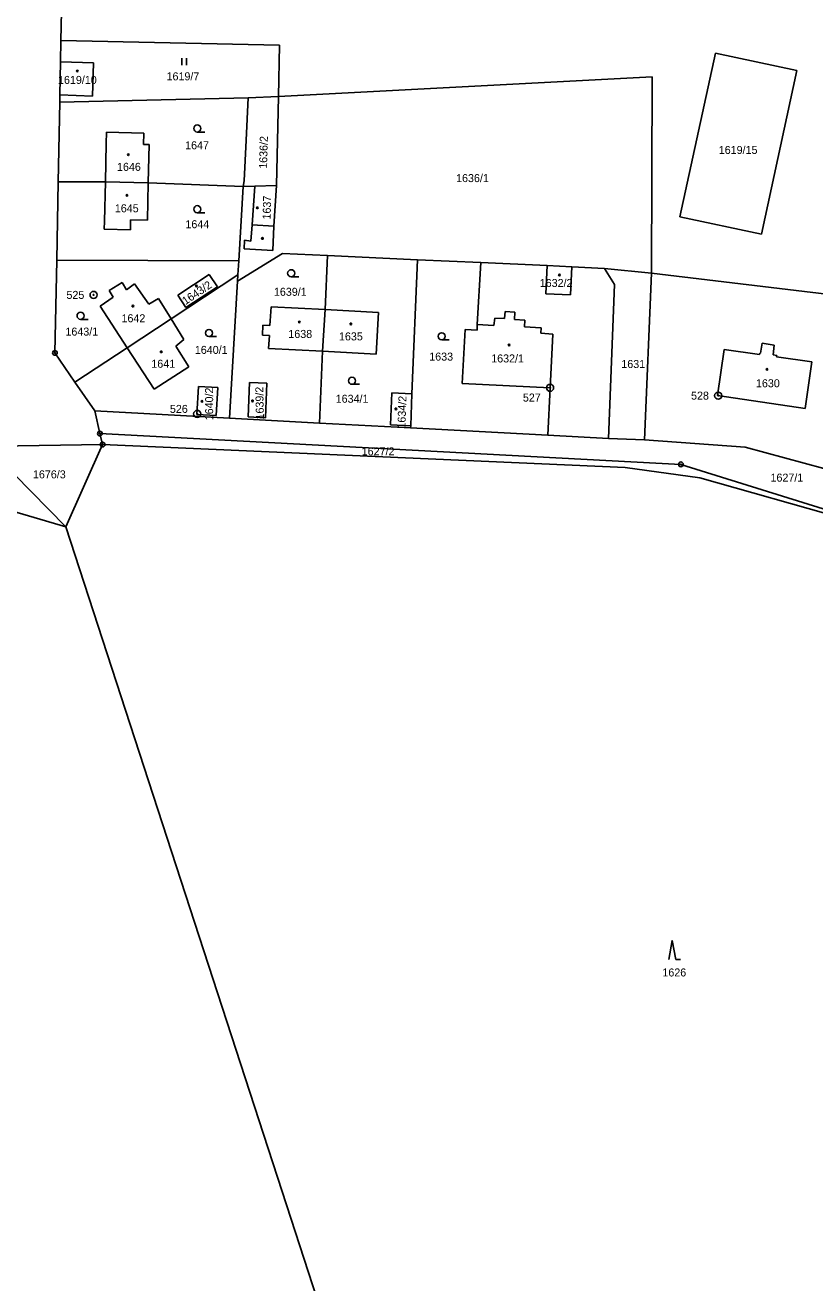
# Model space of a CAD drawing. Extents: x -763296 to -761805, y -1153670 to -1152034.
# Drawn here: x -762755.5 to -762587.9, y -1153075 to -1152808 of the extents above; entities that cross this region are included whole.
import ezdxf

# ---------------------------------------------------------------- set-up
doc = ezdxf.new("R2010")
doc.units = 0
for name, color, linetype in [('Vrstva 1', 7, 'Continuous'), ('Vrstva 13', 7, 'Continuous'), ('Vrstva 17', 7, 'Continuous'), ('Vrstva 18', 7, 'Continuous'), ('Vrstva 19', 7, 'Continuous'), ('Vrstva 24', 7, 'Continuous'), ('Vrstva 25', 7, 'Continuous'), ('Vrstva 4', 7, 'Continuous'), ('Vrstva 6', 7, 'Continuous')]:
    doc.layers.add(name, color=color, linetype=linetype)

msp = doc.modelspace()

# ---------------------------------------------------------------- linework, layer by layer
at = {"layer": 'Vrstva 1'}
for p, q in [((-762747.54, -1152790.8), (-762747.92, -1152811.23)), ((-762747.92, -1152811.23), (-762748.01, -1152815.75)), ((-762747.92, -1152811.23), (-762701.5, -1152812.19)), ((-762701.5, -1152812.19), (-762701.74, -1152823.08)), ((-762748.01, -1152815.75), (-762748.15, -1152822.79)), ((-762748.01, -1152815.75), (-762740.96, -1152815.98)), ((-762740.96, -1152815.98), (-762741.2, -1152823.03)), ((-762616.54, -1152848.68), (-762609.02, -1152813.88)), ((-762609.02, -1152813.88), (-762591.74, -1152817.6)), ((-762591.74, -1152817.6), (-762599.19, -1152852.35)), ((-762701.74, -1152823.08), (-762622.4, -1152818.96)), ((-762622.4, -1152818.96), (-762622.59, -1152860.62)), ((-762748.15, -1152822.79), (-762748.17, -1152824.33)), ((-762748.17, -1152824.33), (-762708.14, -1152823.41)), ((-762741.2, -1152823.03), (-762748.15, -1152822.79)), ((-762708.14, -1152823.41), (-762708.57, -1152832.36)), ((-762708.14, -1152823.41), (-762701.74, -1152823.08)), ((-762701.74, -1152823.08), (-762702.15, -1152842.02)), ((-762748.17, -1152824.33), (-762748.49, -1152841.23)), ((-762738.28, -1152833.12), (-762738.22, -1152830.72)), ((-762730.34, -1152830.91), (-762738.22, -1152830.72)), ((-762730.34, -1152830.91), (-762730.4, -1152833.31)), ((-762738.47, -1152841.24), (-762738.28, -1152833.12)), ((-762730.4, -1152833.31), (-762729.18, -1152833.33)), ((-762729.18, -1152833.33), (-762729.37, -1152841.45)), ((-762708.57, -1152832.36), (-762709.01, -1152840.99)), ((-762748.49, -1152841.23), (-762748.8, -1152857.83)), ((-762748.49, -1152841.23), (-762738.47, -1152841.24)), ((-762738.66, -1152849.55), (-762738.47, -1152841.24)), ((-762729.37, -1152841.45), (-762738.47, -1152841.24)), ((-762729.37, -1152841.45), (-762729.52, -1152849.37)), ((-762709.23, -1152842.19), (-762729.37, -1152841.45)), ((-762709.23, -1152842.19), (-762710.15, -1152858.02)), ((-762709.01, -1152840.99), (-762709.23, -1152842.19)), ((-762706.73, -1152842.13), (-762709.23, -1152842.19)), ((-762706.73, -1152842.13), (-762707.33, -1152850.33)), ((-762702.15, -1152842.02), (-762706.73, -1152842.13)), ((-762702.69, -1152850.62), (-762702.15, -1152842.02)), ((-762738.71, -1152851.29), (-762738.66, -1152849.55)), ((-762733.11, -1152849.28), (-762733.16, -1152851.42)), ((-762729.52, -1152849.37), (-762733.11, -1152849.28)), ((-762707.33, -1152850.33), (-762707.57, -1152853.84)), ((-762702.94, -1152855.84), (-762702.69, -1152850.62)), ((-762599.19, -1152852.35), (-762616.54, -1152848.68)), ((-762733.16, -1152851.42), (-762738.71, -1152851.29)), ((-762708.95, -1152853.61), (-762709.03, -1152855.49)), ((-762709.03, -1152855.49), (-762702.94, -1152855.84)), ((-762707.57, -1152853.84), (-762708.95, -1152853.61)), ((-762748.8, -1152857.83), (-762749.17, -1152877.56)), ((-762710.15, -1152858.02), (-762748.8, -1152857.83)), ((-762710.4, -1152862.29), (-762700.85, -1152856.46)), ((-762710.15, -1152858.02), (-762710.33, -1152860.99)), ((-762700.85, -1152856.46), (-762691.31, -1152856.9)), ((-762691.31, -1152856.9), (-762691.85, -1152868.36)), ((-762691.31, -1152856.9), (-762672.23, -1152857.78)), ((-762672.23, -1152857.78), (-762673.46, -1152886.23)), ((-762672.23, -1152857.78), (-762658.76, -1152858.39)), ((-762658.76, -1152858.39), (-762659.55, -1152871.55)), ((-762658.76, -1152858.39), (-762644.69, -1152858.99)), ((-762724.53, -1152870.33), (-762710.33, -1152860.99)), ((-762723.08, -1152865.32), (-762716.43, -1152860.9)), ((-762716.43, -1152860.9), (-762714.71, -1152863.51)), ((-762710.33, -1152860.99), (-762710.4, -1152862.29)), ((-762644.69, -1152858.99), (-762645.02, -1152865)), ((-762639.49, -1152859.25), (-762644.69, -1152858.99)), ((-762639.78, -1152865.25), (-762639.49, -1152859.25)), ((-762632.51, -1152859.6), (-762639.49, -1152859.25)), ((-762630.43, -1152863.01), (-762632.51, -1152859.6)), ((-762622.59, -1152860.62), (-762632.51, -1152859.6)), ((-762624.06, -1152896.02), (-762622.59, -1152860.62)), ((-762572.19, -1152866.66), (-762622.59, -1152860.62)), ((-762737.65, -1152864.31), (-762734.88, -1152862.59)), ((-762734.88, -1152862.59), (-762734.02, -1152864.13)), ((-762734.02, -1152864.13), (-762732.27, -1152862.91)), ((-762732.27, -1152862.91), (-762729.26, -1152867.23)), ((-762714.71, -1152863.51), (-762721.38, -1152867.9)), ((-762710.4, -1152862.29), (-762712.1, -1152891.43)), ((-762631.71, -1152895.74), (-762630.43, -1152863.01)), ((-762739.6, -1152867.64), (-762736.8, -1152865.73)), ((-762736.8, -1152865.73), (-762737.65, -1152864.31)), ((-762729.26, -1152867.23), (-762727.22, -1152865.99)), ((-762727.22, -1152865.99), (-762724.53, -1152870.33)), ((-762721.38, -1152867.9), (-762723.08, -1152865.32)), ((-762645.02, -1152865), (-762639.78, -1152865.25)), ((-762733.85, -1152876.45), (-762739.6, -1152867.64)), ((-762703.54, -1152871.73), (-762703.31, -1152867.76)), ((-762703.31, -1152867.76), (-762691.85, -1152868.36)), ((-762692.37, -1152877.2), (-762691.85, -1152868.36)), ((-762691.85, -1152868.36), (-762680.48, -1152868.96)), ((-762680.48, -1152868.96), (-762680.99, -1152877.79)), ((-762733.85, -1152876.45), (-762724.53, -1152870.33)), ((-762724.53, -1152870.33), (-762721.82, -1152874.71)), ((-762705.16, -1152873.77), (-762705.08, -1152871.64)), ((-762705.08, -1152871.64), (-762703.54, -1152871.73)), ((-762659.58, -1152872.71), (-762659.55, -1152871.55)), ((-762721.82, -1152874.71), (-762723.49, -1152876.12)), ((-762703.66, -1152873.85), (-762705.16, -1152873.77)), ((-762703.82, -1152876.62), (-762703.66, -1152873.85)), ((-762662.78, -1152884.05), (-762662.13, -1152872.57)), ((-762662.13, -1152872.57), (-762659.58, -1152872.71)), ((-762744.94, -1152883.74), (-762749.17, -1152877.56)), ((-762744.94, -1152883.74), (-762733.85, -1152876.45)), ((-762728.1, -1152885.27), (-762733.85, -1152876.45)), ((-762723.49, -1152876.12), (-762720.73, -1152880.49)), ((-762692.37, -1152877.2), (-762703.82, -1152876.62)), ((-762692.37, -1152877.2), (-762693.01, -1152892.45)), ((-762680.99, -1152877.79), (-762692.37, -1152877.2)), ((-762607.13, -1152876.81), (-762608.57, -1152886.61)), ((-762599.65, -1152877.91), (-762607.13, -1152876.81)), ((-762599.05, -1152875.48), (-762599.45, -1152877.63)), ((-762596.51, -1152875.92), (-762599.05, -1152875.48)), ((-762596.74, -1152877.96), (-762596.51, -1152875.92)), ((-762599.6, -1152877.6), (-762599.65, -1152877.91)), ((-762599.45, -1152877.63), (-762599.6, -1152877.6)), ((-762595.99, -1152878.11), (-762596.74, -1152877.96)), ((-762596.03, -1152878.41), (-762595.99, -1152878.11)), ((-762588.55, -1152879.48), (-762596.03, -1152878.41)), ((-762589.94, -1152889.34), (-762588.55, -1152879.48)), ((-762720.73, -1152880.49), (-762728.1, -1152885.27)), ((-762740.73, -1152889.89), (-762744.94, -1152883.74)), ((-762719.03, -1152890.66), (-762718.71, -1152884.67)), ((-762718.71, -1152884.67), (-762714.64, -1152884.89)), ((-762714.64, -1152884.89), (-762714.96, -1152890.88)), ((-762708.15, -1152891.14), (-762707.92, -1152883.81)), ((-762707.92, -1152883.81), (-762704.2, -1152883.98)), ((-762704.2, -1152883.98), (-762704.48, -1152891.33)), ((-762644.11, -1152885), (-762662.78, -1152884.05)), ((-762644.59, -1152895.05), (-762644.11, -1152885)), ((-762677.99, -1152892.82), (-762677.66, -1152886.03)), ((-762677.66, -1152886.03), (-762673.46, -1152886.23)), ((-762673.46, -1152886.23), (-762673.67, -1152893.03)), ((-762608.57, -1152886.61), (-762589.94, -1152889.34)), ((-762712.1, -1152891.43), (-762740.73, -1152889.89)), ((-762739.63, -1152894.69), (-762740.73, -1152889.89)), ((-762714.96, -1152890.88), (-762719.03, -1152890.66)), ((-762693.01, -1152892.45), (-762712.1, -1152891.43)), ((-762704.48, -1152891.33), (-762708.15, -1152891.14)), ((-762693.01, -1152892.45), (-762673.69, -1152893.49)), ((-762673.67, -1152893.03), (-762677.99, -1152892.82)), ((-762673.67, -1152893.03), (-762673.69, -1152893.49)), ((-762673.69, -1152893.49), (-762644.59, -1152895.05)), ((-762739.05, -1152897.03), (-762739.63, -1152894.69)), ((-762739.63, -1152894.69), (-762616.34, -1152901.22)), ((-762644.59, -1152895.05), (-762631.71, -1152895.74)), ((-762631.71, -1152895.74), (-762624.06, -1152896.02)), ((-762624.06, -1152896.02), (-762602.71, -1152897.57)), ((-762763.69, -1152897.37), (-762739.05, -1152897.03)), ((-762739.05, -1152897.03), (-762746.86, -1152914.48)), ((-762739.05, -1152897.03), (-762628.15, -1152901.89)), ((-762577.03, -1152904.55), (-762602.71, -1152897.57)), ((-762616.34, -1152901.22), (-762557.73, -1152919.56)), ((-762628.15, -1152901.89), (-762612.33, -1152904.1)), ((-762612.33, -1152904.1), (-762557.73, -1152919.56))]:
    msp.add_line(p, q, dxfattribs=at)
at = {"layer": 'Vrstva 13'}
for p, q in [((-762792.7, -1152901.01), (-762746.86, -1152914.48)), ((-762746.86, -1152914.48), (-762699.07, -1153061.5)), ((-762699.07, -1153061.5), (-762691.8, -1153083.85))]:
    msp.add_line(p, q, dxfattribs=at)
at = {"layer": 'Vrstva 24'}
for centre, radius in [((-762740.98, -1152865.24), 0.75), ((-762740.98, -1152865.24), 0.1), ((-762749.17, -1152877.56), 0.5), ((-762749.17, -1152877.56), 0.1), ((-762644.09, -1152884.97), 0.75), ((-762644.09, -1152884.97), 0.1), ((-762608.42, -1152886.63), 0.75), ((-762608.42, -1152886.63), 0.1), ((-762718.99, -1152890.51), 0.75), ((-762718.99, -1152890.51), 0.1), ((-762739.63, -1152894.69), 0.5), ((-762739.63, -1152894.69), 0.1), ((-762739.05, -1152897.03), 0.5), ((-762739.05, -1152897.03), 0.1), ((-762616.34, -1152901.22), 0.5), ((-762616.34, -1152901.22), 0.1)]:
    msp.add_circle(centre, radius, dxfattribs=at)
at = {"layer": 'Vrstva 25'}
for p, q in [((-762722.25, -1152816.47), (-762722.25, -1152814.97)), ((-762721.25, -1152816.47), (-762721.25, -1152814.97)), ((-762718.97, -1152830.65), (-762717.37, -1152830.65)), ((-762718.97, -1152847.79), (-762717.37, -1152847.79)), ((-762699.04, -1152861.39), (-762697.44, -1152861.39)), ((-762743.74, -1152870.43), (-762742.14, -1152870.43)), ((-762716.48, -1152874.08), (-762714.88, -1152874.08)), ((-762667.1, -1152874.78), (-762665.5, -1152874.78)), ((-762686.14, -1152884.22), (-762684.54, -1152884.22))]:
    msp.add_line(p, q, dxfattribs=at)
msp.add_lwpolyline([(-762618.89, -1153006.33), (-762618.19, -1153002.33), (-762617.39, -1153006.33), (-762616.39, -1153006.33)], dxfattribs=at)
for centre, radius in [((-762744.43, -1152817.71), 0.175), ((-762718.97, -1152829.9), 0.75), ((-762733.61, -1152835.47), 0.175), ((-762733.87, -1152844.09), 0.175), ((-762718.97, -1152847.04), 0.75), ((-762706.21, -1152846.75), 0.175), ((-762705.14, -1152853.25), 0.175), ((-762699.04, -1152860.64), 0.75), ((-762642.1, -1152861), 0.175), ((-762719.14, -1152863.36), 0.175), ((-762743.74, -1152869.68), 0.75), ((-762732.63, -1152867.62), 0.175), ((-762697.31, -1152871), 0.175), ((-762686.38, -1152871.39), 0.175), ((-762716.48, -1152873.33), 0.75), ((-762667.1, -1152874.03), 0.75), ((-762726.62, -1152877.33), 0.175), ((-762652.78, -1152875.88), 0.175), ((-762686.14, -1152883.47), 0.75), ((-762598.06, -1152881.03), 0.175), ((-762717.98, -1152887.83), 0.175), ((-762707.25, -1152887.75), 0.175), ((-762676.82, -1152889.44), 0.175)]:
    msp.add_circle(centre, radius, dxfattribs=at)
at = {"layer": 'Vrstva 4'}
for p, q in [((-762707.33, -1152850.33), (-762702.69, -1152850.62)), ((-762653.8, -1152870.28), (-762653.59, -1152868.75)), ((-762653.59, -1152868.75), (-762651.56, -1152868.88)), ((-762651.56, -1152868.88), (-762651.65, -1152870.46)), ((-762659.55, -1152871.55), (-762656.05, -1152871.72)), ((-762656.05, -1152871.72), (-762655.85, -1152870.18)), ((-762655.85, -1152870.18), (-762653.8, -1152870.28)), ((-762651.65, -1152870.46), (-762649.42, -1152870.61)), ((-762649.42, -1152870.61), (-762649.49, -1152871.99)), ((-762649.49, -1152871.99), (-762646, -1152872.24)), ((-762646, -1152872.24), (-762646.04, -1152873.33)), ((-762646.04, -1152873.33), (-762643.5, -1152873.56)), ((-762643.5, -1152873.56), (-762644.11, -1152885))]:
    msp.add_line(p, q, dxfattribs=at)
at = {"layer": 'Vrstva 6'}
msp.add_line((-762746.86, -1152914.48), (-762763.69, -1152897.37), dxfattribs=at)

# ---------------------------------------------------------------- texts
at = {"layer": 'Vrstva 17'}
for s, p in [('525', (-762746.734, -1152866.09)), ('527', (-762649.864, -1152887.89)), ('528', (-762614.174, -1152887.48)), ('526', (-762724.777, -1152890.3))]:
    msp.add_text(s, height=1.7, dxfattribs=at).set_placement(p)
at = {"layer": 'Vrstva 18'}
for s, p in [('1619/7', (-762725.486, -1152819.68)), ('1647', (-762721.545, -1152834.32)), ('1619/15', (-762608.295, -1152835.31)), ('1636/1', (-762664.043, -1152841.29)), ('1644', (-762721.485, -1152851.08)), ('1639/1', (-762702.703, -1152865.43)), ('1643/1', (-762746.953, -1152873.88)), ('1640/1', (-762719.483, -1152877.77)), ('1633', (-762669.739, -1152879.19)), ('1631', (-762628.974, -1152880.76)), ('1634/1', (-762689.593, -1152888.14)), ('1627/2', (-762684.072, -1152899.31)), ('1676/3', (-762753.841, -1152904.19)), ('1627/1', (-762597.31, -1152904.89)), ('1626', (-762620.259, -1153009.96))]:
    msp.add_text(s, height=1.7, dxfattribs=at).set_placement(p)
msp.add_text('1636/2', height=1.7, rotation=88.46468, dxfattribs=at).set_placement((-762704.165, -1152838.484))
at = {"layer": 'Vrstva 19'}
for s, p in [('1619/10', (-762748.524, -1152820.44)), ('1646', (-762736.005, -1152838.9)), ('1645', (-762736.462, -1152847.7)), ('1632/2', (-762646.289, -1152863.56)), ('1642', (-762735.049, -1152871.05)), ('1638', (-762699.643, -1152874.38)), ('1635', (-762688.899, -1152874.9)), ('1641', (-762728.717, -1152880.71)), ('1632/1', (-762656.587, -1152879.58)), ('1630', (-762600.399, -1152884.85))]:
    msp.add_text(s, height=1.7, dxfattribs=at).set_placement(p)
for s, rotation, p in [('1637', 88.52198, (-762703.41, -1152849.251)), ('1643/2', 33.9191, (-762721.475, -1152867.426)), ('1640/2', 90.18356, (-762715.588, -1152891.865)), ('1639/2', 91.10029, (-762704.824, -1152891.674)), ('1634/2', 87.94902, (-762674.811, -1152893.653))]:
    msp.add_text(s, height=1.7, rotation=rotation, dxfattribs=at).set_placement(p)

doc.saveas('drawing.dxf')
